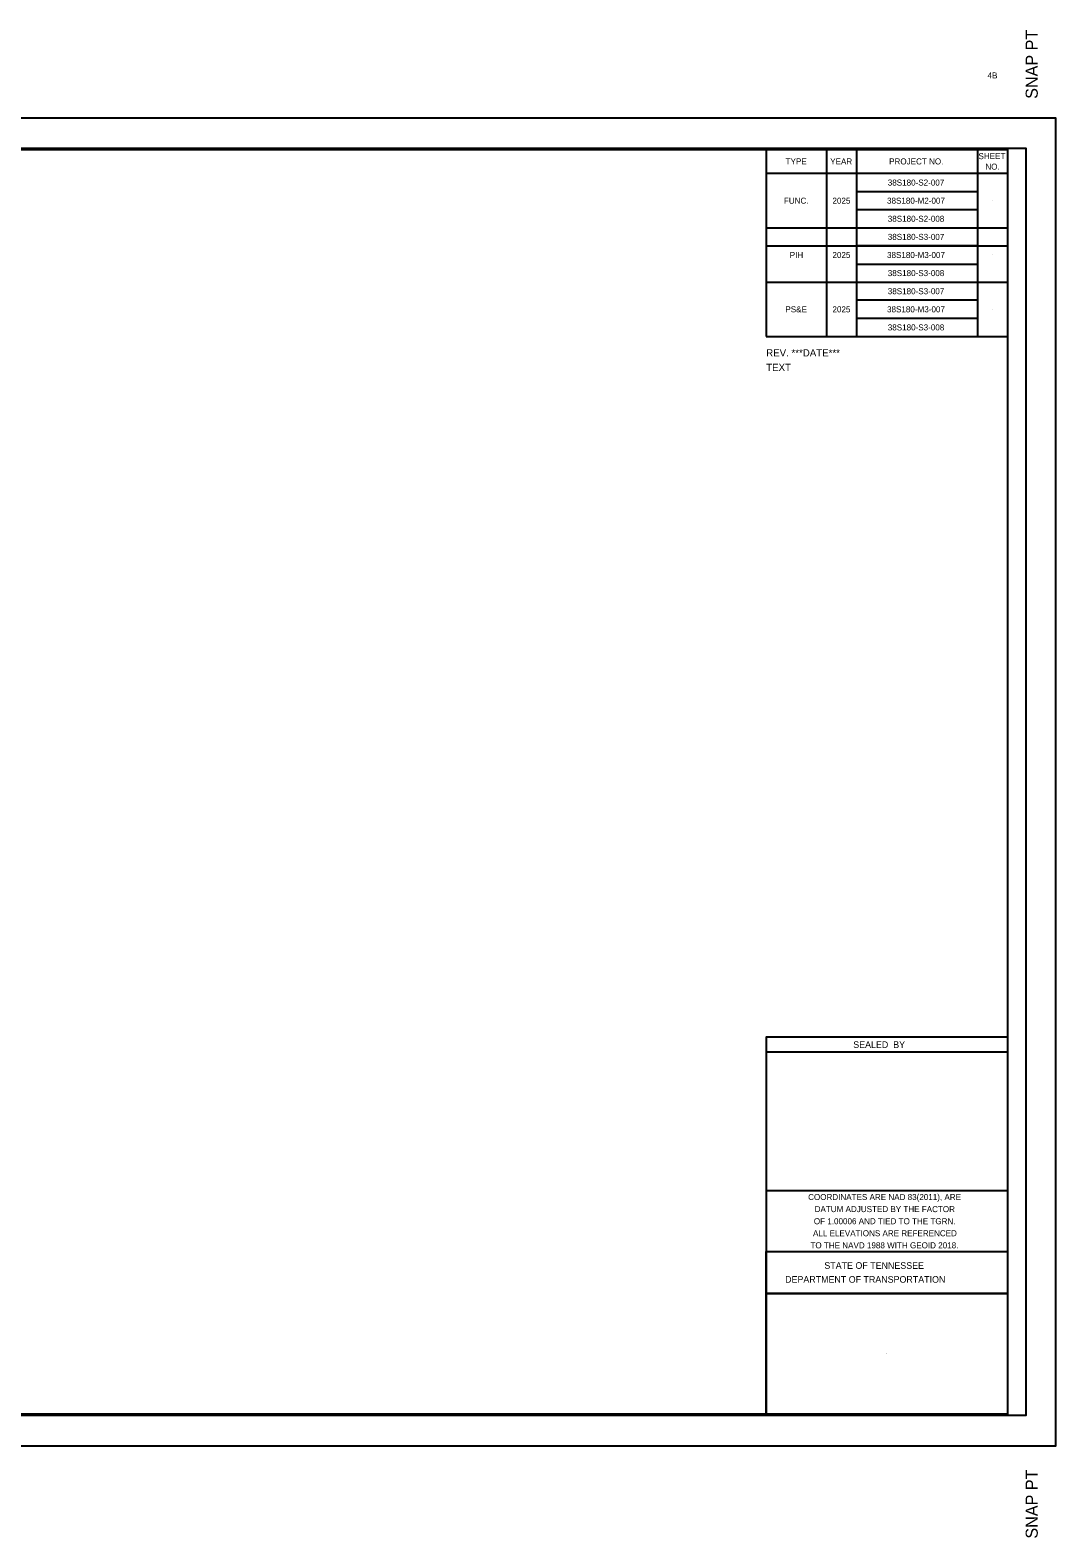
# Model space of a CAD drawing. Extents: x 0 to 2.83, y -0.13 to 1.95.
# Drawn here: x 1.417 to 2.833, y -0.127 to 1.955 of the extents above; entities that cross this region are included whole.
import ezdxf

# ---------------------------------------------------------------- set-up
doc = ezdxf.new("R2010")
doc.units = 0
for name, color, linetype in [('DES - SCRATCH - User 1', 7, 'Continuous'), ('DES - SHEET - Linework', 7, 'Continuous'), ('DES - SHEET - Revision Text', 7, 'Continuous'), ('DES - SHEET - Seal Box', 7, 'Continuous'), ('SUR - UTL - Owners', 7, 'Continuous')]:
    doc.layers.add(name, color=color, linetype=linetype)

msp = doc.modelspace()

# ---------------------------------------------------------------- linework, layer by layer
at = {"layer": 'DES - SCRATCH - User 1'}
for p, q in [((2.6417, 1.7442), (2.6417, 1.7442)), ((2.475, 1.7192), (2.475, 1.7192)), ((2.5375, 1.7192), (2.5375, 1.7192)), ((2.6417, 1.7192), (2.6417, 1.7192)), ((2.7458, 1.7192), (2.7458, 1.7192)), ((2.6417, 1.6942), (2.6417, 1.6942)), ((2.475, 1.6442), (2.475, 1.6442)), ((2.5375, 1.6442), (2.5375, 1.6442)), ((2.6417, 1.6442), (2.6417, 1.6442)), ((2.7458, 1.6442), (2.7458, 1.6442)), ((2.475, 1.5692), (2.475, 1.5692)), ((2.5375, 1.5692), (2.5375, 1.5692)), ((2.6417, 1.5692), (2.6417, 1.5692)), ((2.7458, 1.5692), (2.7458, 1.5692)), ((2.6, 0.1272), (2.6, 0.1272)), ((2.6, 0.1267), (2.6, 0.1267))]:
    msp.add_line(p, q, dxfattribs=at)
at = {"layer": 'DES - SHEET - Linework'}
for p, q in [((2.4333, 1.79), (2.7667, 1.79)), ((2.4333, 1.79), (2.4333, 1.5317)), ((2.5167, 1.79), (2.5167, 1.5317)), ((2.5583, 1.5317), (2.5583, 1.79)), ((2.725, 1.79), (2.725, 1.5317)), ((2.7667, 1.79), (2.7667, 1.6817)), ((2.7667, 1.7567), (2.4333, 1.7567)), ((2.5583, 1.7317), (2.725, 1.7317)), ((2.725, 1.7067), (2.5583, 1.7067)), ((2.4333, 1.6817), (2.7667, 1.6817)), ((2.725, 1.6567), (2.5583, 1.6567)), ((2.5583, 1.6317), (2.725, 1.6317)), ((2.4333, 1.6067), (2.7667, 1.6067)), ((2.725, 1.5817), (2.5583, 1.5817)), ((2.5583, 1.5567), (2.725, 1.5567)), ((2.4333, 1.5317), (2.7667, 1.5317))]:
    msp.add_line(p, q, dxfattribs=at)
for points in [[(0, 0), (2.8333, 0), (2.8333, 1.8333), (0, 1.8333)], [(0.1, 1.79), (2.7667, 1.79), (2.7667, 0.0433), (0.1, 0.0433)], [(2.4333, 1.79), (2.4333, 1.6567), (2.7667, 1.6567), (2.7667, 0.5642), (2.4333, 0.5642), (2.4333, 0.0433), (0.1, 0.0433), (0.1, 1.79)], [(2.7667, 0.21), (2.4333, 0.21), (2.4333, 0.2683), (2.7667, 0.2683)], [(2.7667, 0.0433), (2.4333, 0.0433), (2.4333, 0.21), (2.7667, 0.21)]]:
    msp.add_lwpolyline(points, close=True, dxfattribs=at)
at = {"layer": 'DES - SHEET - Revision Text'}
msp.add_lwpolyline([(0.0417, 1.7917), (2.7917, 1.7917), (2.7917, 0.0417), (0.0417, 0.0417)], close=True, dxfattribs=at)
at = {"layer": 'DES - SHEET - Seal Box'}
for p, q in [((2.7667, 0.5642), (2.4333, 0.5642)), ((2.4333, 0.5642), (2.4333, 0.3517)), ((2.7667, 0.5642), (2.7667, 0.3517)), ((2.7667, 0.5433), (2.4333, 0.5433)), ((2.7667, 0.3517), (2.4333, 0.3517))]:
    msp.add_line(p, q, dxfattribs=at)

# ---------------------------------------------------------------- texts
at = {"layer": 'DES - SCRATCH - User 1'}
for s, p in [('COORDINATES ARE NAD 83(2011), ARE', (2.4912, 0.3392)), ('OF 1.00006 AND TIED TO THE TGRN.', (2.4991, 0.3058)), ('DATUM ADJUSTED BY THE FACTOR', (2.5002, 0.3225)), ('ALL ELEVATIONS ARE REFERENCED', (2.4979, 0.2892)), ('TO THE NAVD 1988 WITH GEOID 2018.', (2.4944, 0.2725))]:
    msp.add_text(s, height=0.008333, rotation=360, dxfattribs=at).set_placement(p)
at = {"layer": 'DES - SHEET - Revision Text'}
for s, p in [('REV. ***DATE***', (2.4333, 1.504)), ('TEXT ', (2.4333, 1.484))]:
    msp.add_text(s, height=0.01, dxfattribs=at).set_placement(p)
at = {"layer": 'DES - SHEET - Seal Box'}
msp.add_text('SEALED  BY', height=0.00917, rotation=360, dxfattribs=at).set_placement((2.5535, 0.5492))
at = {"layer": 'SUR - UTL - Owners'}
for s, height, rotation, p in [('           SNAP PT', 0.016667, 90, (2.8083, 1.7917)), ('4B', 0.00833, 360, (2.739, 1.8879)), ('TYPE', 0.00833, 360, (2.4601, 1.7692)), ('YEAR', 0.00833, 360, (2.5217, 1.7692)), ('PROJECT NO.', 0.008333, 360, (2.6031, 1.7692)), ('SHEET', 0.00833, 360, (2.7265, 1.7765)), ('NO.', 0.00833, 360, (2.736, 1.762)), ('38S180-S2-007', 0.008333, 360, (2.6012, 1.74)), ('FUNC.', 0.00833, 360, (2.4577, 1.715)), ('2025', 0.00833, 360, (2.5248, 1.715)), ('38S180-M2-007', 0.008333, 360, (2.6002, 1.715)), ('38S180-S2-008', 0.008333, 360, (2.6012, 1.69)), ('38S180-S3-007', 0.008333, 360, (2.6012, 1.665)), ('PIH', 0.00833, 360, (2.4658, 1.64)), ('2025', 0.00833, 360, (2.5248, 1.64)), ('38S180-M3-007', 0.008333, 360, (2.6002, 1.64)), ('38S180-S3-008', 0.008333, 360, (2.6012, 1.615)), ('38S180-S3-007', 0.008333, 360, (2.6012, 1.59)), ('PS&E', 0.00833, 360, (2.4598, 1.565)), ('2025', 0.00833, 360, (2.5248, 1.565)), ('38S180-M3-007', 0.008333, 360, (2.6002, 1.565)), ('38S180-S3-008', 0.008333, 360, (2.6012, 1.54)), ('STATE OF TENNESSEE', 0.009167, 360, (2.5136, 0.2442)), ('DEPARTMENT OF TRANSPORTATION', 0.009167, 360, (2.4594, 0.225)), ('SNAP PT           ', 0.016667, 90, (2.8083, -0.1283))]:
    msp.add_text(s, height=height, rotation=rotation, dxfattribs=at).set_placement(p)

doc.saveas('drawing.dxf')
